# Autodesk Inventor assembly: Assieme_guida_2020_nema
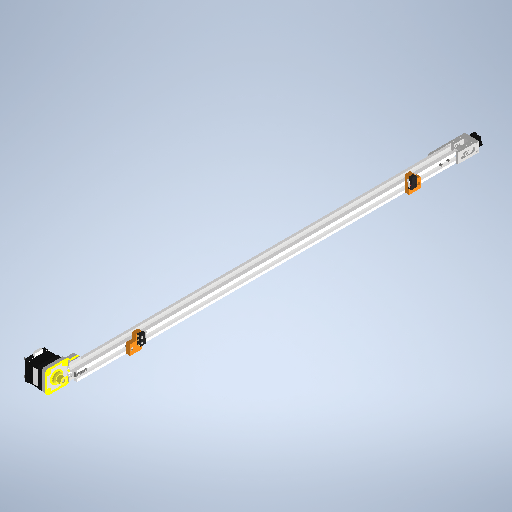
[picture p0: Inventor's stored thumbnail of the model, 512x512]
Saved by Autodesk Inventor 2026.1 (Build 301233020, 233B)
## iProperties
Created: 2026-01
Part Number: Assieme_guida_2020_nema
Document SubType Name: Assembly
Designer: hp
Sending System: Autodesk Inventor 2025
Preprocessor: ST-DEVELOPER v20
Title: Assieme_guida_2020_nema.stp
Author: R5800u
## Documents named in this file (17)
- C:\Users\hp\Documents\Inventor\DOM1_CartesianRobot\Assieme_guida_2020_nema - Copy.iam
- C:\Users\hp\Documents\Inventor\DOM1_CartesianRobot\2020 Belt Tensioner G_K.iam
- C:\Users\hp\Documents\Inventor\DOM1_CartesianRobot\GT2_20T.ipt
- C:\Users\hp\Documents\Inventor\DOM1_CartesianRobot\NO-NC Limit Switch.ipt
- C:\Users\hp\Documents\Inventor\DOM1_CartesianRobot\blocco_sensore.ipt
- C:\Users\hp\Documents\Inventor\DOM1_CartesianRobot\blocco_sensore_MIR.ipt
- C:\Users\hp\Documents\Inventor\DOM1_CartesianRobot\NEMA 42SHDC3030Z.ipt
- C:\Users\hp\Documents\Inventor\DOM1_CartesianRobot\blocco_nema.ipt
- C:\Users\hp\Documents\Inventor\DOM1_CartesianRobot\2020v2.ipt
- C:\Users\hp\Documents\Inventor\Content Center Files\R2026\en-US\ISO 4762(2)\ISO 4762 - M4 x 25ISO.ipt
- C:\Users\hp\Documents\Inventor\Content Center Files\R2026\en-US\ISO 4762(2)\ISO 4762 - M3 x 25ISO.ipt
- C:\Users\hp\Documents\Inventor\Content Center Files\R2026\en-US\ISO 4017(1)\ISO 4017 - M4 x 25 - ISO.ipt
- C:\Users\hp\Documents\Inventor\DOM1_CartesianRobot\2020 M4 (1).ipt
- C:\Users\hp\Documents\Inventor\Content Center Files\R2026\en-US\ANSI B18.3.1M(5)\ANSI B18.3.1M - M3x0.5 x 45(3).ipt
- C:\Users\hp\Documents\Inventor\Content Center Files\R2026\en-US\ISO 4032(2)\ISO 4032 - M3 - ISO.ipt
- C:\Users\hp\Documents\Inventor\DOM1_CartesianRobot\2020 M3.ipt
- C:\Users\hp\Documents\Inventor\Content Center Files\R2026\en-US\ISO 4017(1)\ISO 4017 - M2 x 8 - ISO.ipt
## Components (31 placed, 16 different names)
1. 2020:1
2. 2020 Belt Tensioner G_K:1 [sub-assembly]
3. GT2_20T:1 — Rigid:1
4. NO-NC Limit Switch:1 — Mate:9, Mate:10, Mate:11, Mate:80, Mate:81, Mate:82, Mate:83
5. NO-NC Limit Switch:2 — Mate:17, Mate:18, Mate:19
6. blocco_sensore:1
7. blocco_sensore_MIR:1 — Mate:15, Mate:16, Mate:17, Mate:18, Mate:19
8. NEMA 42SHDC3030Z:1
9. blocco_nema:1
10. ISO 4762 M3 x 25:1 — Mate:32, Mate:33, Mate:76
11. ISO 4762 M3 x 25:2 — Mate:34, Mate:35, Mate:77
12. ISO 4017 M2 x 8:1 — Mate:80, Mate:81
13. ISO 4017 M4 x 25:1 — Mate:40, Mate:41
14. ISO 4017 M4 x 25:2 — Mate:42, Mate:43
15. 2020 M4 (1):1 — Mate:44, Angle:1, Mate:51
16. 2020 M4 (1):2 — Mate:45, Angle:2, Mate:50
17. ISO 4762 M4 x 25:1 — Mate:46, Mate:47, Mate:50
18. ISO 4762 M4 x 25:2 — Mate:48, Mate:49, Mate:51
19. Drilled Forged Hexagon Socket Head Cap Screw - 6 Holes - Metric M3x0.5 x 45:1 — Mate:52, Mate:53
20. ISO 4032 M3:1 — Mate:60, Mate:61
21. Drilled Forged Hexagon Socket Head Cap Screw - 6 Holes - Metric M3x0.5 x 45:2 — Mate:54, Mate:55
22. Drilled Forged Hexagon Socket Head Cap Screw - 6 Holes - Metric M3x0.5 x 45:3 — Mate:56, Mate:57
23. Drilled Forged Hexagon Socket Head Cap Screw - 6 Holes - Metric M3x0.5 x 45:4 — Mate:58, Mate:59
24. ISO 4032 M3:2 — Mate:62, Mate:63
25. ISO 4032 M3:3 — Mate:64, Mate:65
26. ISO 4032 M3:4 — Mate:66, Mate:67
27. 2020 M3:1 — Mate:72, Angle:3
28. 2020 M3:2 — Mate:73, Angle:4
29. 2020 M3:5 — Mate:75, Angle:5, Mate:77
30. 2020 M3:6 — Mate:74, Angle:6, Mate:76
31. ISO 4017 M2 x 8:2 — Mate:82, Mate:83
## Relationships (57: Mate 50, Angle 6, WeldJoint 1)
- Rigid:1 [WeldJoint]: GT2_20T:1
- Mate:9: NO-NC Limit Switch:1
- Mate:10: NO-NC Limit Switch:1
- Mate:11: NO-NC Limit Switch:1
- Mate:15: blocco_sensore_MIR:1
- Mate:16: blocco_sensore_MIR:1
- Mate:17: NO-NC Limit Switch:2 ↔ blocco_sensore_MIR:1
- Mate:18: NO-NC Limit Switch:2 ↔ blocco_sensore_MIR:1
- Mate:19: NO-NC Limit Switch:2 ↔ blocco_sensore_MIR:1
- Mate:32: ISO 4762 M3 x 25:1
- Mate:33: ISO 4762 M3 x 25:1
- Mate:34: ISO 4762 M3 x 25:2
- Mate:35: ISO 4762 M3 x 25:2
- Mate:40: ISO 4017 M4 x 25:1
- Mate:41: ISO 4017 M4 x 25:1
- Mate:42: ISO 4017 M4 x 25:2
- Mate:43: ISO 4017 M4 x 25:2
- Mate:44: 2020 M4 (1):1
- Mate:45: 2020 M4 (1):2
- Angle:1: 2020 M4 (1):1
- Angle:2: 2020 M4 (1):2
- Mate:46: ISO 4762 M4 x 25:1
- Mate:47: ISO 4762 M4 x 25:1
- Mate:48: ISO 4762 M4 x 25:2
- Mate:49: ISO 4762 M4 x 25:2
- Mate:50: 2020 M4 (1):2 ↔ ISO 4762 M4 x 25:1
- Mate:51: 2020 M4 (1):1 ↔ ISO 4762 M4 x 25:2
- Mate:52: Drilled Forged Hexagon Socket Head Cap Screw - 6 Holes - Metric M3x0.5 x 45:1
- Mate:53: Drilled Forged Hexagon Socket Head Cap Screw - 6 Holes - Metric M3x0.5 x 45:1
- Mate:54: Drilled Forged Hexagon Socket Head Cap Screw - 6 Holes - Metric M3x0.5 x 45:2
- Mate:55: Drilled Forged Hexagon Socket Head Cap Screw - 6 Holes - Metric M3x0.5 x 45:2
- Mate:56: Drilled Forged Hexagon Socket Head Cap Screw - 6 Holes - Metric M3x0.5 x 45:3
- Mate:57: Drilled Forged Hexagon Socket Head Cap Screw - 6 Holes - Metric M3x0.5 x 45:3
- Mate:58: Drilled Forged Hexagon Socket Head Cap Screw - 6 Holes - Metric M3x0.5 x 45:4
- Mate:59: Drilled Forged Hexagon Socket Head Cap Screw - 6 Holes - Metric M3x0.5 x 45:4
- Mate:60: ISO 4032 M3:1
- Mate:61: ISO 4032 M3:1
- Mate:62: ISO 4032 M3:2
- Mate:63: ISO 4032 M3:2
- Mate:64: ISO 4032 M3:3
- Mate:65: ISO 4032 M3:3
- Mate:66: ISO 4032 M3:4
- Mate:67: ISO 4032 M3:4
- Mate:72: 2020 M3:1
- Mate:73: 2020 M3:2
- Angle:3: 2020 M3:1
- Angle:4: 2020 M3:2
- Mate:74: 2020 M3:6
- Mate:75: 2020 M3:5
- Angle:5: 2020 M3:5
- Angle:6: 2020 M3:6
- Mate:76: ISO 4762 M3 x 25:1 ↔ 2020 M3:6
- Mate:77: ISO 4762 M3 x 25:2 ↔ 2020 M3:5
- Mate:80: NO-NC Limit Switch:1 ↔ ISO 4017 M2 x 8:1
- Mate:81: NO-NC Limit Switch:1 ↔ ISO 4017 M2 x 8:1
- Mate:82: NO-NC Limit Switch:1 ↔ ISO 4017 M2 x 8:2
- Mate:83: NO-NC Limit Switch:1 ↔ ISO 4017 M2 x 8:2
